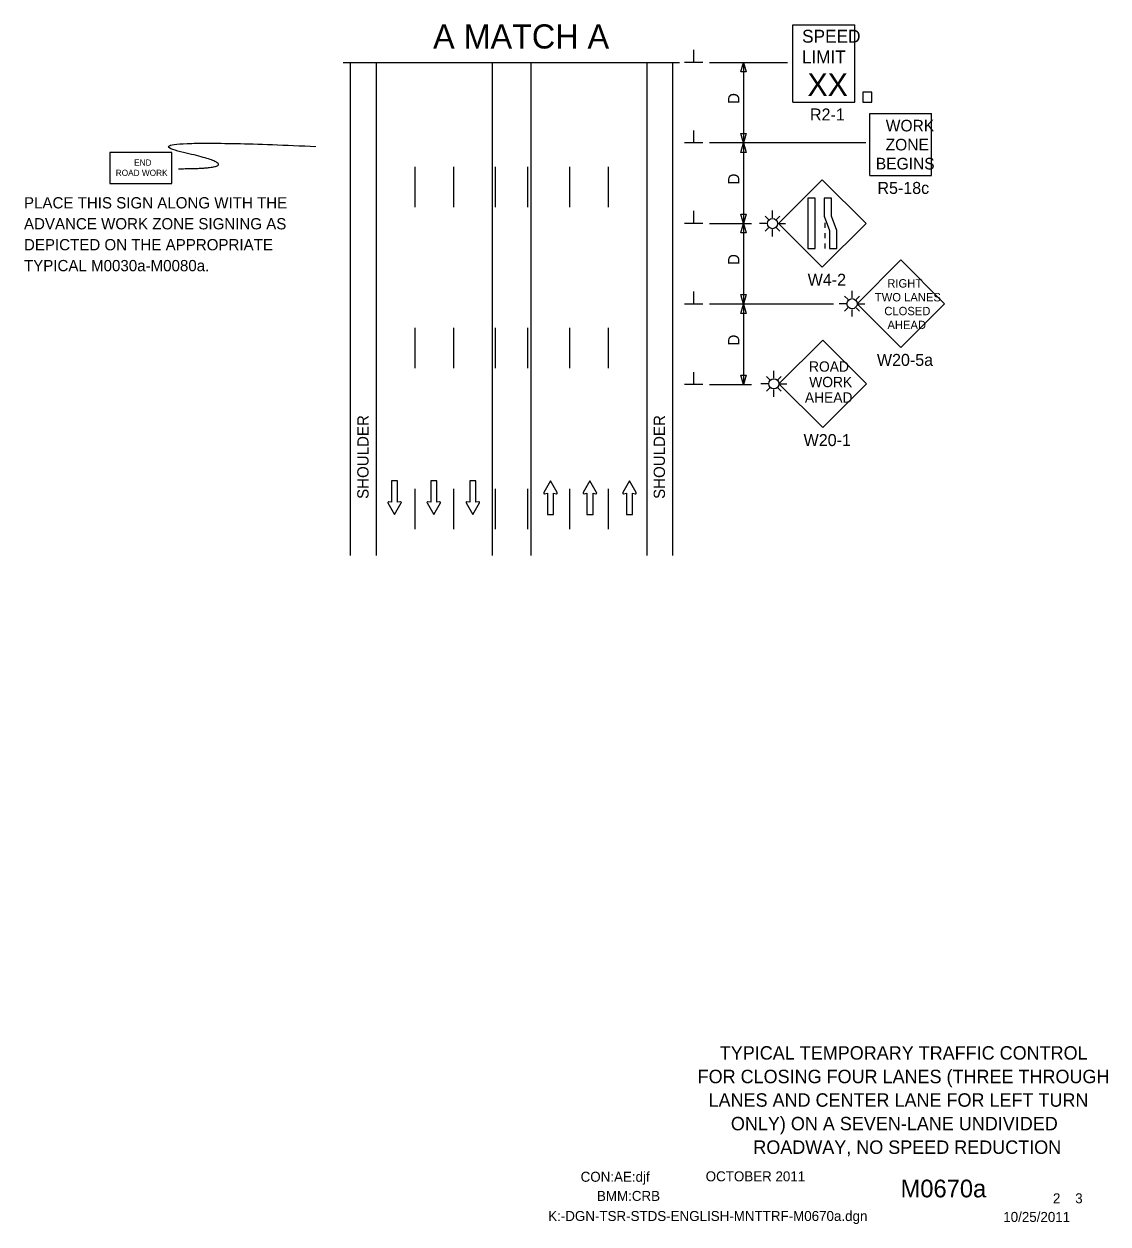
# Model space of a CAD drawing. Extents: x 16038 to 19504, y 5920 to 8321.
# Drawn here: x 17774 to 18447, y 7218 to 7963 of the extents above; entities that cross this region are included whole.
import ezdxf

# ---------------------------------------------------------------- set-up
doc = ezdxf.new("R2010")
doc.units = 0
for name, color, linetype in [('ALI_LEGAL_EX', 7, 'Continuous'), ('BORDER', 7, 'Continuous'), ('BORDER_SIGNAL_WO', 7, 'Continuous'), ('MT_SCRATCH_LEVEL_E', 7, 'Continuous'), ('PAVT_EDGE_EX', 7, 'Continuous'), ('TRAFFIC_SIGNS_PR', 7, 'Continuous'), ('TYPICAL_TEXT_DIMEN_PR', 7, 'Continuous')]:
    doc.layers.add(name, color=color, linetype=linetype)

msp = doc.modelspace()

# ---------------------------------------------------------------- linework, layer by layer
at = {"layer": 'ALI_LEGAL_EX'}
for points in [[(18016.73, 7874.49), (18016.73, 7849.49)], [(18040.73, 7874.49), (18040.73, 7849.49)], [(18066.73, 7874.49), (18066.73, 7849.49)], [(18086.73, 7874.49), (18086.73, 7849.49)], [(18112.73, 7874.49), (18112.73, 7849.49)], [(18136.73, 7874.49), (18136.73, 7849.49)], [(18016.73, 7774.49), (18016.73, 7749.49)], [(18040.73, 7774.49), (18040.73, 7749.49)], [(18066.73, 7774.49), (18066.73, 7749.49)], [(18086.73, 7774.49), (18086.73, 7749.49)], [(18112.73, 7774.49), (18112.73, 7749.49)], [(18136.73, 7774.49), (18136.73, 7749.49)], [(18016.73, 7674.49), (18016.73, 7649.49)], [(18040.73, 7674.49), (18040.73, 7649.49)], [(18066.73, 7674.49), (18066.73, 7649.49)], [(18086.73, 7674.49), (18086.73, 7649.49)], [(18112.73, 7674.49), (18112.73, 7649.49)], [(18136.73, 7674.49), (18136.73, 7649.49)]]:
    msp.add_lwpolyline(points, dxfattribs=at)
at = {"layer": 'BORDER'}
for p, q in [((18318.25, 7297.5), (18318.25, 7297.5)), ((18318.25, 7291.25), (18318.25, 7291.25))]:
    msp.add_line(p, q, dxfattribs=at)
at = {"layer": 'MT_SCRATCH_LEVEL_E'}
for p, q in [((18006.14, 7679.44), (18002.4, 7679.44)), ((18002.4, 7679.44), (18002.4, 7666.18)), ((18006.14, 7679.44), (18002.4, 7679.44)), ((18002.4, 7679.44), (18002.4, 7666.18)), ((18006.14, 7666.18), (18006.14, 7679.44)), ((18006.14, 7666.18), (18006.14, 7679.44)), ((18030.4, 7679.44), (18026.65, 7679.44)), ((18026.65, 7679.44), (18026.65, 7666.18)), ((18030.4, 7679.44), (18026.65, 7679.44)), ((18026.65, 7679.44), (18026.65, 7666.18)), ((18030.4, 7666.18), (18030.4, 7679.44)), ((18030.4, 7666.18), (18030.4, 7679.44)), ((18054.65, 7679.44), (18050.91, 7679.44)), ((18050.91, 7679.44), (18050.91, 7666.18)), ((18054.65, 7679.44), (18050.91, 7679.44)), ((18050.91, 7679.44), (18050.91, 7666.18)), ((18054.65, 7666.18), (18054.65, 7679.44)), ((18054.65, 7666.18), (18054.65, 7679.44)), ((18100.97, 7679.44), (18096.86, 7672.2)), ((18100.97, 7679.44), (18096.86, 7672.2)), ((18105.12, 7672.2), (18100.97, 7679.44)), ((18105.12, 7672.2), (18100.97, 7679.44)), ((18125.47, 7679.44), (18121.36, 7672.2)), ((18125.47, 7679.44), (18121.36, 7672.2)), ((18129.61, 7672.2), (18125.47, 7679.44)), ((18129.61, 7672.2), (18125.47, 7679.44)), ((18149.96, 7679.44), (18145.85, 7672.2)), ((18149.96, 7679.44), (18145.85, 7672.2)), ((18154.11, 7672.2), (18149.96, 7679.44)), ((18154.11, 7672.2), (18149.96, 7679.44)), ((18097.34, 7671.52), (18099.12, 7671.83)), ((18097.34, 7671.52), (18099.12, 7671.83)), ((18099.12, 7671.83), (18099.12, 7658.57)), ((18099.12, 7671.83), (18099.12, 7658.57)), ((18102.86, 7658.57), (18102.86, 7671.83)), ((18102.86, 7671.83), (18104.64, 7671.52)), ((18102.86, 7658.57), (18102.86, 7671.83)), ((18102.86, 7671.83), (18104.64, 7671.52)), ((18121.84, 7671.52), (18123.62, 7671.83)), ((18121.84, 7671.52), (18123.62, 7671.83)), ((18123.62, 7671.83), (18123.62, 7658.57)), ((18123.62, 7671.83), (18123.62, 7658.57)), ((18127.36, 7658.57), (18127.36, 7671.83)), ((18127.36, 7671.83), (18129.14, 7671.52)), ((18127.36, 7658.57), (18127.36, 7671.83)), ((18127.36, 7671.83), (18129.14, 7671.52)), ((18146.33, 7671.52), (18148.11, 7671.83)), ((18146.33, 7671.52), (18148.11, 7671.83)), ((18148.11, 7671.83), (18148.11, 7658.57)), ((18148.11, 7671.83), (18148.11, 7658.57)), ((18151.85, 7658.57), (18151.85, 7671.83)), ((18151.85, 7671.83), (18153.63, 7671.52)), ((18151.85, 7658.57), (18151.85, 7671.83)), ((18151.85, 7671.83), (18153.63, 7671.52)), ((18000.14, 7665.81), (18004.29, 7658.57)), ((18000.14, 7665.81), (18004.29, 7658.57)), ((18002.4, 7666.18), (18000.62, 7666.5)), ((18002.4, 7666.18), (18000.62, 7666.5)), ((18004.29, 7658.57), (18008.4, 7665.81)), ((18004.29, 7658.57), (18008.4, 7665.81)), ((18007.92, 7666.5), (18006.14, 7666.18)), ((18007.92, 7666.5), (18006.14, 7666.18)), ((18024.4, 7665.81), (18028.55, 7658.57)), ((18024.4, 7665.81), (18028.55, 7658.57)), ((18026.65, 7666.18), (18024.88, 7666.5)), ((18026.65, 7666.18), (18024.88, 7666.5)), ((18028.55, 7658.57), (18032.66, 7665.81)), ((18028.55, 7658.57), (18032.66, 7665.81)), ((18032.17, 7666.5), (18030.4, 7666.18)), ((18032.17, 7666.5), (18030.4, 7666.18)), ((18048.65, 7665.81), (18052.8, 7658.57)), ((18048.65, 7665.81), (18052.8, 7658.57)), ((18050.91, 7666.18), (18049.13, 7666.5)), ((18050.91, 7666.18), (18049.13, 7666.5)), ((18052.8, 7658.57), (18056.91, 7665.81)), ((18052.8, 7658.57), (18056.91, 7665.81)), ((18056.43, 7666.5), (18054.65, 7666.18)), ((18056.43, 7666.5), (18054.65, 7666.18)), ((18099.12, 7658.57), (18102.86, 7658.57)), ((18099.12, 7658.57), (18102.86, 7658.57)), ((18123.62, 7658.57), (18127.36, 7658.57)), ((18123.62, 7658.57), (18127.36, 7658.57)), ((18148.11, 7658.57), (18151.85, 7658.57)), ((18148.11, 7658.57), (18151.85, 7658.57))]:
    msp.add_line(p, q, dxfattribs=at)
for centre, start, end in [((18097.27, 7671.97), 150.42484, 279.96381), ((18097.27, 7671.97), 150.42484, 279.96381), ((18104.71, 7671.98), 260.03619, 29.77312), ((18104.71, 7671.98), 260.03619, 29.77312), ((18121.76, 7671.97), 150.42484, 279.96381), ((18121.76, 7671.97), 150.42484, 279.96381), ((18129.2, 7671.98), 260.03619, 29.77312), ((18129.2, 7671.98), 260.03619, 29.77312), ((18146.26, 7671.97), 150.42484, 279.96381), ((18146.26, 7671.97), 150.42484, 279.96381), ((18153.7, 7671.98), 260.03619, 29.77312), ((18153.7, 7671.98), 260.03619, 29.77312), ((18000.55, 7666.04), 80.03619, 209.77312), ((18000.55, 7666.04), 80.03619, 209.77312), ((18007.99, 7666.04), 330.42484, 99.96381), ((18007.99, 7666.04), 330.42484, 99.96381), ((18024.81, 7666.04), 80.03619, 209.77312), ((18024.81, 7666.04), 80.03619, 209.77312), ((18032.25, 7666.04), 330.42484, 99.96381), ((18032.25, 7666.04), 330.42484, 99.96381), ((18049.06, 7666.04), 80.03619, 209.77312), ((18049.06, 7666.04), 80.03619, 209.77312), ((18056.5, 7666.04), 330.42484, 99.96381), ((18056.5, 7666.04), 330.42484, 99.96381)]:
    msp.add_arc(centre, 0.463, start, end, dxfattribs=at)
at = {"layer": 'PAVT_EDGE_EX'}
for p, q in [((17976.73, 7939.31), (17976.73, 7633.14)), ((17992.73, 7939.31), (17992.73, 7633.14)), ((18064.73, 7939.31), (18064.73, 7633.14)), ((18088.73, 7939.31), (18088.73, 7633.14)), ((18160.73, 7939.31), (18160.73, 7633.14)), ((18176.73, 7939.31), (18176.73, 7633.14))]:
    msp.add_line(p, q, dxfattribs=at)
at = {"layer": 'TRAFFIC_SIGNS_PR'}
for p, q in [((18251.34, 7962.71), (18289.74, 7962.71)), ((18251.34, 7914.71), (18251.34, 7962.71)), ((18289.74, 7914.71), (18289.74, 7962.71)), ((18251.34, 7914.71), (18289.74, 7914.71)), ((18299.05, 7869.11), (18299.05, 7907.51)), ((18299.05, 7907.51), (18337.45, 7907.51)), ((18337.45, 7869.11), (18337.45, 7907.51)), ((18299.05, 7869.11), (18337.45, 7869.11)), ((18269.62, 7866.41), (18242.47, 7839.26)), ((18296.77, 7839.26), (18269.62, 7866.41)), ((18238.75, 7842.77), (18238.75, 7847.27)), ((18235.6, 7839.22), (18230.77, 7839.22)), ((18236.24, 7841.73), (18234.13, 7843.84)), ((18241.26, 7841.73), (18243.36, 7843.84)), ((18241.9, 7839.22), (18246.77, 7839.22)), ((18242.47, 7839.26), (18269.62, 7812.11)), ((18269.62, 7812.11), (18296.77, 7839.26)), ((18271.26, 7839.75), (18271.26, 7836.55)), ((18236.24, 7836.71), (18234.13, 7834.61)), ((18238.75, 7831.27), (18238.75, 7835.67)), ((18241.26, 7836.71), (18243.36, 7834.61)), ((18271.26, 7833.35), (18271.26, 7830.15)), ((18271.26, 7826.95), (18271.26, 7823.75)), ((18318.4, 7816.65), (18291.25, 7789.49)), ((18345.56, 7789.49), (18318.4, 7816.65)), ((18285.59, 7792.01), (18283.48, 7794.11)), ((18288.1, 7793.05), (18288.1, 7797.55)), ((18290.61, 7792.01), (18292.72, 7794.11)), ((18284.94, 7789.49), (18280.11, 7789.49)), ((18285.58, 7786.98), (18283.48, 7784.87)), ((18290.61, 7786.98), (18292.72, 7784.87)), ((18291.25, 7789.49), (18296.13, 7789.49)), ((18291.25, 7789.49), (18318.4, 7762.34)), ((18318.4, 7762.34), (18345.56, 7789.49)), ((18288.1, 7781.53), (18288.1, 7785.94)), ((18269.88, 7766.93), (18242.7, 7739.74)), ((18297.07, 7739.74), (18269.88, 7766.93)), ((18237.03, 7742.26), (18234.92, 7744.37)), ((18239.54, 7743.3), (18239.54, 7747.8)), ((18242.06, 7742.26), (18244.17, 7744.37)), ((18236.39, 7739.74), (18231.55, 7739.74)), ((18237.03, 7737.23), (18234.92, 7735.12)), ((18239.54, 7731.78), (18239.54, 7736.19)), ((18242.06, 7737.23), (18244.16, 7735.12)), ((18242.7, 7739.74), (18247.58, 7739.74)), ((18242.7, 7739.74), (18269.88, 7712.56)), ((18269.88, 7712.56), (18297.07, 7739.74))]:
    msp.add_line(p, q, dxfattribs=at)
for points in [[(18294.75, 7914.71), (18300.35, 7914.71), (18300.35, 7920.88), (18294.75, 7920.88)], [(17827.61, 7864.09), (17866.01, 7864.09), (17866.01, 7883.29), (17827.61, 7883.29)], [(18260.72, 7855), (18260.72, 7823.75), (18265.22, 7823.75), (18265.22, 7855)], [(18270.86, 7855), (18270.86, 7843.82), (18274.2, 7834.93), (18274.2, 7823.75), (18278.7, 7823.75), (18278.7, 7834.93), (18275.35, 7843.82), (18275.35, 7855)]]:
    msp.add_lwpolyline(points, close=True, dxfattribs=at)
for centre in [(18238.75, 7839.22), (18288.1, 7789.49), (18239.54, 7739.75)]:
    msp.add_circle(centre, 3.15, dxfattribs=at)
msp.add_open_spline([(17870.15, 7873.33), (17917.38, 7873.33), (17832.36, 7892.67), (17955.46, 7887.18)], degree=2, dxfattribs=at)
at = {"layer": 'TYPICAL_TEXT_DIMEN_PR'}
for p, q in [((18189.85, 7939.31), (18189.85, 7947.09)), ((17972.43, 7939.31), (18181.03, 7939.31)), ((18064.73, 7939.31), (18088.73, 7939.31)), ((18195.48, 7939.31), (18184.23, 7939.31)), ((18199.73, 7939.31), (18248, 7939.31)), ((18199.73, 7939.31), (18225.73, 7939.31)), ((18219.16, 7933.45), (18220.73, 7939.31)), ((18220.73, 7939.31), (18222.3, 7933.45)), ((18220.73, 7939.31), (18220.73, 7889.31)), ((18220.73, 7933.45), (18219.16, 7933.45)), ((18222.3, 7933.45), (18220.73, 7933.45)), ((18189.85, 7889.31), (18189.85, 7897.09)), ((18220.73, 7889.31), (18219.16, 7895.17)), ((18219.16, 7895.17), (18220.73, 7895.17)), ((18220.73, 7895.17), (18222.3, 7895.17)), ((18222.3, 7895.17), (18220.73, 7889.31)), ((18195.48, 7889.31), (18184.23, 7889.31)), ((18296.59, 7889.31), (18199.73, 7889.31)), ((18219.16, 7883.45), (18220.73, 7889.31)), ((18220.73, 7883.45), (18219.16, 7883.45)), ((18220.73, 7889.31), (18222.3, 7883.45)), ((18220.73, 7889.31), (18220.73, 7839.31)), ((18222.3, 7883.45), (18220.73, 7883.45)), ((18189.85, 7839.31), (18189.85, 7847.09)), ((18195.48, 7839.31), (18184.23, 7839.31)), ((18199.73, 7839.31), (18225.73, 7839.31)), ((18199.73, 7839.31), (18225.73, 7839.31)), ((18220.73, 7839.31), (18219.16, 7845.17)), ((18219.16, 7845.17), (18220.73, 7845.17)), ((18219.16, 7833.45), (18220.73, 7839.31)), ((18220.73, 7845.17), (18222.3, 7845.17)), ((18222.3, 7845.17), (18220.73, 7839.31)), ((18220.73, 7839.31), (18222.3, 7833.45)), ((18220.73, 7839.31), (18220.73, 7789.31)), ((18220.73, 7833.45), (18219.16, 7833.45)), ((18222.3, 7833.45), (18220.73, 7833.45)), ((18189.85, 7789.31), (18189.85, 7797.09)), ((18220.73, 7789.31), (18219.16, 7795.17)), ((18219.16, 7795.17), (18220.73, 7795.17)), ((18220.73, 7795.17), (18222.3, 7795.17)), ((18222.3, 7795.17), (18220.73, 7789.31)), ((18195.48, 7789.31), (18184.23, 7789.31)), ((18276.53, 7789.31), (18199.73, 7789.31)), ((18219.16, 7783.45), (18220.73, 7789.31)), ((18220.73, 7789.31), (18222.3, 7783.45)), ((18220.73, 7789.31), (18220.73, 7739.31)), ((18220.73, 7783.45), (18219.16, 7783.45)), ((18222.3, 7783.45), (18220.73, 7783.45)), ((18189.85, 7739.31), (18189.85, 7747.09)), ((18220.73, 7739.31), (18219.16, 7745.17)), ((18219.16, 7745.17), (18220.73, 7745.17)), ((18220.73, 7745.17), (18222.3, 7745.17)), ((18222.3, 7745.17), (18220.73, 7739.31)), ((18195.48, 7739.31), (18184.23, 7739.31)), ((18199.73, 7739.31), (18225.73, 7739.31))]:
    msp.add_line(p, q, dxfattribs=at)

# ---------------------------------------------------------------- texts
at = {"layer": 'BORDER'}
for s, p in [('TYPICAL TEMPORARY TRAFFIC CONTROL', (18206.02, 7320.15)), ('FOR CLOSING FOUR LANES (THREE THROUGH', (18192.29, 7305.52)), ('LANES AND CENTER LANE FOR LEFT TURN', (18199.07, 7290.89)), ('ONLY) ON A SEVEN-LANE UNDIVIDED', (18212.91, 7276.26)), ('ROADWAY, NO SPEED REDUCTION', (18226.83, 7261.63))]:
    msp.add_text(s, height=8.348, dxfattribs=at).set_placement(p)
at = {"layer": 'BORDER_SIGNAL_WO'}
for s, height, p in [('CON:AE:djf', 6.2, (18119.69, 7244.31)), ('    OCTOBER 2011    ', 6.2, (18188.08, 7244.59)), ('    M0670a   ', 11, (18301.86, 7234.63)), ('BMM:CRB   ', 6.2, (18129.81, 7232.42)), (' 2    3 ', 6.2, (18410.45, 7230.95)), ('K:-DGN-TSR-STDS-ENGLISH-MNTTRF-M0670a.dgn        ', 6.2, (18099.55, 7219.96)), ('10/25/2011    ', 6.2, (18381.93, 7219.38))]:
    msp.add_text(s, height=height, dxfattribs=at).set_placement(p)
at = {"layer": 'TRAFFIC_SIGNS_PR'}
for s, height, p in [('SPEED', 8, (18257.1, 7951.57)), ('LIMIT', 8, (18256.94, 7938.77)), ('XX', 14.031, (18260.45, 7918.47)), ('R2-1', 7.44, (18262.01, 7903.27)), ('WORK', 7.217, (18309.05, 7896.47)), ('ZONE', 7.217, (18308.94, 7884.66)), ('END', 3.831, (17842.61, 7875.22)), ('BEGINS', 7.217, (18302.86, 7872.86)), ('ROAD WORK', 3.831, (17831.22, 7868.84)), ('R5-18c', 7.44, (18303.87, 7857.67)), ('PLACE THIS SIGN ALONG WITH THE', 7, (17774.28, 7848.65)), ('ADVANCE WORK ZONE SIGNING AS', 7, (17774.28, 7835.65)), ('DEPICTED ON THE APPROPRIATE', 7, (17774.28, 7822.65)), ('TYPICAL M0030a-M0080a.', 7, (17774.28, 7809.65)), ('W4-2', 7.44, (18260.58, 7800.67)), ('RIGHT', 5.2, (18309.98, 7799.53)), ('TWO LANES', 5.2, (18302.26, 7790.93)), ('CLOSED', 5.2, (18308.12, 7782.33)), ('AHEAD', 5.2, (18310.06, 7773.73)), ('W20-5a', 7.44, (18303.54, 7750.9)), ('ROAD', 6.408, (18261.41, 7747.29)), ('WORK', 6.408, (18261.52, 7737.68)), ('AHEAD', 6.408, (18258.83, 7728.07)), ('W20-1', 7.449, (18258.04, 7701.11))]:
    msp.add_text(s, height=height, dxfattribs=at).set_placement(p)
at = {"layer": 'TYPICAL_TEXT_DIMEN_PR'}
msp.add_text('A MATCH A', height=15, dxfattribs=at).set_placement((18028.14, 7947.95))
for s, p in [('D', (18218.17, 7913.53)), ('D', (18218.17, 7863.53)), ('D', (18218.17, 7813.53)), ('D', (18218.17, 7763.53)), ('SHOULDER', (17988.1, 7668.3)), ('SHOULDER', (18172.01, 7668.3))]:
    msp.add_text(s, height=7, rotation=90, dxfattribs=at).set_placement(p)

doc.saveas('drawing.dxf')
